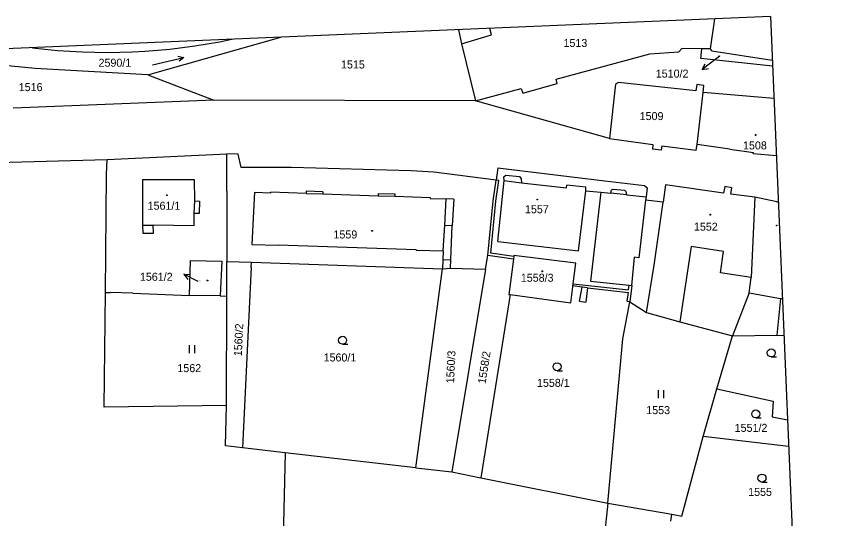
# Model space of a CAD drawing. Extents: x -806456 to -805395, y -1150847 to -1150506.
# Drawn here: x -805548.5 to -805394.6, y -1150600.2 to -1150506.1 of the extents above; entities that cross this region are included whole.
import ezdxf

# ---------------------------------------------------------------- set-up
doc = ezdxf.new("R2010")
doc.units = 0
for name, color, linetype in [('Default', 7, 'Continuous'), ('formát', 7, 'Continuous'), ('kn_celek - Cisla parcel pomocna', 7, 'Continuous'), ('kn_celek - Cisla pozemkovych parcel', 7, 'Continuous'), ('kn_celek - Cisla stavebnich parcel', 7, 'Continuous'), ('kn_celek - Hranice parcel', 7, 'Continuous'), ('kn_celek - Vnitrni kresby', 7, 'Continuous'), ('kn_celek - Znacky budov', 7, 'Continuous'), ('kn_celek - Znacky kultur', 7, 'Continuous')]:
    doc.layers.add(name, color=color, linetype=linetype)

# ---------------------------------------------------------------- blocks, each defined once
blk = doc.blocks.new('304')
at = {"layer": 'Default'}
blk.add_line((-0.1, 0), (9.9, 0), dxfattribs=at)
blk.add_circle((-0.1, 7.5), 7.5, dxfattribs=at)
blk = doc.blocks.new('306')
at = {"layer": 'Default'}
for p, q in [((-5.2, 0), (-5.2, 15)), ((4.8, 0), (4.8, 15))]:
    blk.add_line(p, q, dxfattribs=at)
blk = doc.blocks.new('402')
at = {"layer": 'Default'}
for p, q in [((-0.8, 0.8), (0.7, 0.8)), ((-0.8, 0.8), (-0.8, -0.7)), ((0.7, 0.8), (0.7, -0.7)), ((0.7, -0.7), (-0.8, -0.7))]:
    blk.add_line(p, q, dxfattribs=at)
blk = doc.blocks.new('Z61')
at = {"layer": 'Default'}
for p, q in [((0, 0), (30, 0)), ((30, 0), (19.2, 5.3)), ((30, 0), (19.2, -5.3))]:
    blk.add_line(p, q, dxfattribs=at)
blk = doc.blocks.new('802')
at = {"layer": 'Default'}
for p, q in [((-30, 0), (30, 0)), ((20, 5), (30, 0)), ((30, 0), (20, -5))]:
    blk.add_line(p, q, dxfattribs=at)

msp = doc.modelspace()

# ---------------------------------------------------------------- linework, layer by layer
at = {"layer": 'formát'}
for q in [(-805617.02, -1150514.97), (-805394.61, -1150802.8)]:
    msp.add_line((-805407.21, -1150506.06), q, dxfattribs=at)
at = {"layer": 'kn_celek - Cisla parcel pomocna'}
msp.add_line((-805416.7, -1150513.5), (-805417.6, -1150514.2), dxfattribs=at)
at = {"layer": 'kn_celek - Hranice parcel'}
for p, q in [((-805418.45, -1150512.13), (-805417.6, -1150506.5)), ((-805465.68, -1150508.55), (-805465.08, -1150511.17)), ((-805459.51, -1150509.54), (-805459.82, -1150508.3)), ((-805523.89, -1150516.99), (-805498.97, -1150509.96)), ((-805465.08, -1150511.17), (-805459.51, -1150509.54)), ((-805465.08, -1150511.17), (-805462.51, -1150521.87)), ((-805424.36, -1150512.68), (-805423.78, -1150512.05)), ((-805420.06, -1150512.11), (-805423.78, -1150512.05)), ((-805420.27, -1150513.95), (-805420.06, -1150512.11)), ((-805418.45, -1150512.13), (-805420.06, -1150512.11)), ((-805418.16, -1150512.5), (-805418.45, -1150512.13)), ((-805545.02, -1150515.82), (-805573.69, -1150513.13)), ((-805434.17, -1150514.23), (-805429.79, -1150513.09)), ((-805429.79, -1150513.09), (-805424.36, -1150512.68)), ((-805406.81, -1150515.36), (-805420.27, -1150513.95)), ((-805418.16, -1150512.5), (-805406.86, -1150514.24)), ((-805447.37, -1150517.8), (-805434.17, -1150514.23)), ((-805523.89, -1150516.99), (-805545.02, -1150515.82)), ((-805523.89, -1150516.99), (-805511.56, -1150521.75)), ((-805447.18, -1150518.66), (-805447.37, -1150517.8)), ((-805435.67, -1150518.44), (-805436.25, -1150518.74)), ((-805421.2, -1150520), (-805435.67, -1150518.44)), ((-805462.51, -1150521.87), (-805453.91, -1150519.58)), ((-805453.91, -1150519.58), (-805453.6, -1150520.47)), ((-805453.6, -1150520.47), (-805447.18, -1150518.66)), ((-805436.25, -1150518.74), (-805437.39, -1150528.93)), ((-805420.99, -1150518.84), (-805421.2, -1150520)), ((-805419.68, -1150518.99), (-805420.99, -1150518.84)), ((-805419.83, -1150520.32), (-805419.68, -1150518.99)), ((-805420.95, -1150530.06), (-805419.83, -1150520.32)), ((-805406.55, -1150521.42), (-805419.83, -1150520.32)), ((-805511.56, -1150521.75), (-805549.13, -1150523.27)), ((-805462.51, -1150521.87), (-805511.56, -1150521.75)), ((-805437.39, -1150528.93), (-805462.51, -1150521.87)), ((-805437.39, -1150528.93), (-805429.24, -1150530.06)), ((-805429.24, -1150530.06), (-805429.33, -1150530.91)), ((-805427.7, -1150531.12), (-805429.33, -1150530.91)), ((-805427.53, -1150530.33), (-805427.7, -1150531.12)), ((-805427.53, -1150530.33), (-805421.13, -1150531.13)), ((-805421.13, -1150531.13), (-805420.95, -1150530.06)), ((-805414.8, -1150530.96), (-805420.95, -1150530.06)), ((-805414.8, -1150530.96), (-805410.39, -1150531.59)), ((-805531.55, -1150532.9), (-805509.09, -1150531.8)), ((-805506.98, -1150531.87), (-805509.09, -1150531.8)), ((-805509.09, -1150534.77), (-805509.09, -1150531.8)), ((-805506.43, -1150534.35), (-805506.98, -1150531.87)), ((-805410.42, -1150531.81), (-805410.39, -1150531.59)), ((-805406.1, -1150532.2), (-805410.42, -1150531.81)), ((-805552.74, -1150533.48), (-805531.55, -1150532.9)), ((-805531.63, -1150535.7), (-805531.55, -1150532.9)), ((-805509.1, -1150538.82), (-805509.09, -1150534.77)), ((-805496.95, -1150534.39), (-805506.43, -1150534.35)), ((-805492.41, -1150534.52), (-805496.95, -1150534.39)), ((-805479.1, -1150534.87), (-805492.41, -1150534.52)), ((-805474.57, -1150534.98), (-805479.1, -1150534.87)), ((-805470.31, -1150535.26), (-805474.57, -1150534.98)), ((-805458.6, -1150536.72), (-805470.31, -1150535.26)), ((-805458.32, -1150534.47), (-805458.6, -1150536.72)), ((-805458.32, -1150534.47), (-805442.37, -1150536.36)), ((-805531.85, -1150557.78), (-805531.63, -1150535.7)), ((-805459.17, -1150540.62), (-805458.6, -1150536.72)), ((-805442.37, -1150536.36), (-805438.22, -1150536.87)), ((-805438.22, -1150536.87), (-805430.82, -1150537.74)), ((-805430.82, -1150537.74), (-805430.33, -1150538.18)), ((-805430.33, -1150538.18), (-805430.52, -1150539.85)), ((-805426.87, -1150537.61), (-805427.33, -1150540.86)), ((-805416.02, -1150539.19), (-805426.87, -1150537.61)), ((-805415.77, -1150537.95), (-805416.02, -1150539.19)), ((-805414.46, -1150538.19), (-805415.77, -1150537.95)), ((-805414.59, -1150539.39), (-805414.46, -1150538.19)), ((-805509.1, -1150538.82), (-805509.12, -1150551.97)), ((-805430.52, -1150539.85), (-805430.6, -1150540.49)), ((-805410.1, -1150539.94), (-805414.59, -1150539.39)), ((-805410.1, -1150539.94), (-805410.81, -1150554.99)), ((-805405.98, -1150540.8), (-805410.1, -1150539.94)), ((-805460.18, -1150550.87), (-805459.17, -1150540.62)), ((-805430.6, -1150540.49), (-805431.86, -1150551.3)), ((-805427.33, -1150540.86), (-805430.6, -1150540.49)), ((-805405.98, -1150540.8), (-805405.73, -1150540.83)), ((-805460.61, -1150553.45), (-805460.18, -1150550.87)), ((-805455.39, -1150551.57), (-805460.18, -1150550.87)), ((-805455.3, -1150550.87), (-805455.32, -1150551.04)), ((-805443.69, -1150552.31), (-805455.3, -1150550.87)), ((-805516.08, -1150558.34), (-805515.92, -1150551.82)), ((-805515.92, -1150551.82), (-805510.02, -1150551.94)), ((-805510.02, -1150551.94), (-805510.34, -1150558.45)), ((-805509.13, -1150558.47), (-805509.12, -1150551.97)), ((-805509.12, -1150551.97), (-805504.5, -1150552.13)), ((-805504.54, -1150553.06), (-805504.5, -1150552.13)), ((-805504.5, -1150552.13), (-805468.7, -1150553.35)), ((-805455.39, -1150551.57), (-805456.22, -1150558.16)), ((-805455.32, -1150551.04), (-805455.39, -1150551.57)), ((-805444.17, -1150556.16), (-805443.69, -1150552.31)), ((-805433.2, -1150556.49), (-805432.65, -1150551.21)), ((-805431.86, -1150551.3), (-805432.65, -1150551.21)), ((-805504.54, -1150553.06), (-805506.16, -1150586.91)), ((-805473.68, -1150590.65), (-805468.7, -1150553.35)), ((-805468.7, -1150553.35), (-805467.17, -1150553.25)), ((-805467.17, -1150553.25), (-805460.61, -1150553.45)), ((-805460.61, -1150553.45), (-805466.95, -1150591.42)), ((-805411.2, -1150557.84), (-805410.81, -1150554.99)), ((-805444.62, -1150559.77), (-805444.24, -1150556.76)), ((-805444.24, -1150556.76), (-805444.22, -1150556.58)), ((-805444.22, -1150556.58), (-805444.17, -1150556.16)), ((-805442.51, -1150556.81), (-805444.22, -1150556.58)), ((-805442.99, -1150559.46), (-805442.51, -1150556.81)), ((-805441.51, -1150556.92), (-805441.79, -1150559.61)), ((-805441.51, -1150556.92), (-805433.8, -1150557.81)), ((-805433.2, -1150556.49), (-805433.55, -1150559.55)), ((-805532.07, -1150579.27), (-805531.85, -1150557.78)), ((-805531.85, -1150557.78), (-805530.91, -1150557.81)), ((-805526.7, -1150557.96), (-805530.91, -1150557.81)), ((-805526.7, -1150557.96), (-805516.08, -1150558.34)), ((-805510.34, -1150558.45), (-805516.08, -1150558.34)), ((-805510.34, -1150558.45), (-805509.13, -1150558.47)), ((-805509.15, -1150578.97), (-805509.13, -1150558.47)), ((-805455.99, -1150558.2), (-805461.49, -1150592.52)), ((-805456.22, -1150558.16), (-805455.99, -1150558.2)), ((-805455.99, -1150558.2), (-805444.62, -1150559.77)), ((-805434.03, -1150559.5), (-805433.8, -1150557.81)), ((-805411.2, -1150557.84), (-805414.3, -1150565.9)), ((-805442.99, -1150559.46), (-805441.79, -1150559.61)), ((-805434.86, -1150566.49), (-805433.55, -1150559.55)), ((-805433.55, -1150559.55), (-805434.03, -1150559.5)), ((-805433.55, -1150559.55), (-805430.41, -1150561.57)), ((-805430.41, -1150561.57), (-805424.21, -1150563.29)), ((-805424.21, -1150563.29), (-805414.3, -1150565.9)), ((-805417.22, -1150575.88), (-805414.3, -1150565.9)), ((-805414.3, -1150565.9), (-805405.97, -1150565.79)), ((-805405.97, -1150565.79), (-805404.67, -1150565.84)), ((-805437.68, -1150597.31), (-805434.86, -1150566.49)), ((-805419.83, -1150584.77), (-805417.22, -1150575.88)), ((-805417.22, -1150575.88), (-805406.71, -1150578.2)), ((-805406.71, -1150578.2), (-805406.9, -1150581.1)), ((-805509.15, -1150578.97), (-805532.07, -1150579.27)), ((-805509.35, -1150586.54), (-805509.15, -1150578.97)), ((-805406.9, -1150581.1), (-805404, -1150581.65)), ((-805423.81, -1150599.71), (-805419.83, -1150584.77)), ((-805403.78, -1150586.66), (-805419.83, -1150584.77)), ((-805506.16, -1150586.91), (-805509.35, -1150586.54)), ((-805498.17, -1150587.83), (-805506.16, -1150586.91)), ((-805498.17, -1150587.83), (-805498.93, -1150623.15)), ((-805473.68, -1150590.65), (-805498.17, -1150587.83)), ((-805473.68, -1150590.65), (-805466.95, -1150591.42)), ((-805466.95, -1150591.42), (-805461.49, -1150592.52)), ((-805461.49, -1150592.52), (-805437.68, -1150597.31)), ((-805437.68, -1150597.31), (-805443.12, -1150647.75)), ((-805437.68, -1150597.31), (-805425.71, -1150599.38)), ((-805425.86, -1150600.64), (-805425.71, -1150599.38)), ((-805425.71, -1150599.38), (-805423.81, -1150599.71))]:
    msp.add_line(p, q, dxfattribs=at)
at = {"layer": 'kn_celek - Vnitrni kresby'}
for p, q in [((-805524.89, -1150536.62), (-805524.91, -1150545.19)), ((-805524.89, -1150536.62), (-805515.24, -1150536.65)), ((-805515.24, -1150536.65), (-805515.19, -1150540.64)), ((-805458.68, -1150540.69), (-805458.11, -1150536.79)), ((-805458.11, -1150536.79), (-805458.6, -1150536.72)), ((-805458.29, -1150548.25), (-805457.14, -1150536.84)), ((-805457.16, -1150536.13), (-805456.81, -1150535.82)), ((-805457.14, -1150536.84), (-805457.16, -1150536.13)), ((-805457.14, -1150536.84), (-805453.89, -1150537.22)), ((-805456.81, -1150535.82), (-805454.24, -1150536.08)), ((-805454.24, -1150536.08), (-805453.91, -1150536.48)), ((-805453.91, -1150536.48), (-805453.89, -1150537.22)), ((-805453.89, -1150537.22), (-805445.44, -1150538.21)), ((-805445.44, -1150538.21), (-805445.38, -1150537.71)), ((-805441.78, -1150538.07), (-805445.38, -1150537.71)), ((-805441.79, -1150538.76), (-805441.78, -1150538.07)), ((-805437.1, -1150539.21), (-805436.96, -1150538.55)), ((-805436.96, -1150538.55), (-805436.65, -1150538.41)), ((-805436.65, -1150538.41), (-805434.57, -1150538.62)), ((-805434.57, -1150538.62), (-805434.31, -1150538.89)), ((-805503.94, -1150539), (-805504.43, -1150548.79)), ((-805503.94, -1150539), (-805500.84, -1150539.11)), ((-805494.21, -1150539.23), (-805500.84, -1150539.01)), ((-805500.84, -1150539.11), (-805500.84, -1150539.01)), ((-805494.2, -1150538.83), (-805494.21, -1150539.23)), ((-805494.21, -1150539.23), (-805491.11, -1150539.33)), ((-805491.1, -1150538.93), (-805494.2, -1150538.83)), ((-805491.1, -1150538.93), (-805491.11, -1150539.33)), ((-805491.11, -1150539.33), (-805480.73, -1150539.67)), ((-805480.73, -1150539.28), (-805477.6, -1150539.3)), ((-805480.73, -1150539.28), (-805480.73, -1150539.67)), ((-805480.73, -1150539.67), (-805477.6, -1150539.77)), ((-805477.6, -1150539.3), (-805477.6, -1150539.77)), ((-805477.6, -1150539.77), (-805470.98, -1150539.99)), ((-805470.98, -1150539.99), (-805470.97, -1150540.17)), ((-805470.97, -1150540.17), (-805468, -1150540.27)), ((-805443.17, -1150549.97), (-805441.79, -1150538.76)), ((-805441.79, -1150538.76), (-805438.99, -1150539.03)), ((-805438.99, -1150539.03), (-805440.91, -1150555.69)), ((-805438.99, -1150539.03), (-805437.1, -1150539.21)), ((-805434.2, -1150539.49), (-805437.1, -1150539.21)), ((-805434.31, -1150538.89), (-805434.2, -1150539.49)), ((-805434.2, -1150539.49), (-805430.52, -1150539.85)), ((-805515.19, -1150540.64), (-805515.27, -1150542.99)), ((-805515.19, -1150540.64), (-805514.21, -1150540.67)), ((-805514.21, -1150540.67), (-805514.27, -1150543)), ((-805468.22, -1150545.16), (-805468, -1150540.27)), ((-805466.52, -1150540.33), (-805468, -1150540.27)), ((-805466.52, -1150540.33), (-805466.84, -1150545.25)), ((-805459.63, -1150550.42), (-805458.68, -1150540.69)), ((-805429.02, -1150552.71), (-805427.33, -1150540.86)), ((-805515.27, -1150542.99), (-805515.31, -1150545.28)), ((-805514.27, -1150543), (-805515.27, -1150542.99)), ((-805524.91, -1150545.19), (-805524.86, -1150546.66)), ((-805524.91, -1150545.19), (-805522.89, -1150545.2)), ((-805515.31, -1150545.28), (-805522.89, -1150545.2)), ((-805522.83, -1150546.66), (-805522.89, -1150545.2)), ((-805468.57, -1150550.01), (-805468.22, -1150545.16)), ((-805468.22, -1150545.16), (-805466.84, -1150545.25)), ((-805467.08, -1150551.6), (-805466.84, -1150545.25)), ((-805524.86, -1150546.66), (-805522.83, -1150546.66)), ((-805504.43, -1150548.79), (-805499.48, -1150548.96)), ((-805499.48, -1150548.86), (-805473.58, -1150549.74)), ((-805499.48, -1150548.96), (-805499.48, -1150548.86)), ((-805458.29, -1150548.25), (-805443.17, -1150549.97)), ((-805422.07, -1150549.17), (-805424.21, -1150563.29)), ((-805415.98, -1150550.09), (-805422.07, -1150549.17)), ((-805473.58, -1150549.84), (-805473.58, -1150549.74)), ((-805473.58, -1150549.84), (-805468.57, -1150550.01)), ((-805468.57, -1150550.01), (-805468.62, -1150551.68)), ((-805455.32, -1150551.04), (-805459.63, -1150550.42)), ((-805416.53, -1150554.11), (-805415.98, -1150550.09)), ((-805468.62, -1150551.68), (-805468.7, -1150553.35)), ((-805468.62, -1150551.68), (-805467.08, -1150551.6)), ((-805467.17, -1150553.25), (-805467.08, -1150551.6)), ((-805430.41, -1150561.57), (-805429.02, -1150552.71)), ((-805410.81, -1150554.99), (-805416.53, -1150554.11)), ((-805444.17, -1150556.16), (-805433.78, -1150557.3)), ((-805441.51, -1150556.92), (-805442.51, -1150556.81)), ((-805440.91, -1150555.69), (-805433.7, -1150556.44)), ((-805433.78, -1150557.3), (-805433.7, -1150556.44)), ((-805433.7, -1150556.44), (-805433.2, -1150556.49)), ((-805411.2, -1150557.84), (-805405.34, -1150558.91)), ((-805405.34, -1150558.91), (-805405.97, -1150565.79)), ((-805405.34, -1150558.91), (-805404.96, -1150558.95))]:
    msp.add_line(p, q, dxfattribs=at)
msp.add_arc((-805531.59, -1150399.65), 113.15, 262.9118, 281.9498, dxfattribs=at)
msp.add_arc((-805531.59, -1150399.65), 113.15, 262.9118, 281.9498, dxfattribs=at)

# ---------------------------------------------------------------- block references
at = {"layer": 'kn_celek - Cisla parcel pomocna'}
for p, xscale, yscale, rotation in [((-805417.6, -1150514.2), 0.1, 0.10000000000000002, -142.35543), ((-805514.48, -1150555.74), 0.09999999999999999, 0.09999999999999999, 153.43497)]:
    msp.add_blockref('Z61', p, dxfattribs=dict(at, xscale=xscale, yscale=yscale, rotation=rotation))
at = {"layer": 'kn_celek - Znacky budov', "xscale": 0.1, "yscale": 0.10000000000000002}
for p in [(-805409.98, -1150528.29), (-805520.35, -1150539.56), (-805450.91, -1150540.38), (-805418.48, -1150543.22), (-805481.89, -1150546.27), (-805406.04, -1150545.24), (-805449.97, -1150553.85), (-805512.76, -1150555.55)]:
    msp.add_blockref('402', p, dxfattribs=at)
at = {"layer": 'kn_celek - Znacky kultur', "xscale": 0.1, "yscale": 0.10000000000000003, "rotation": 13.362932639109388}
msp.add_blockref('802', (-805520.1, -1150514.44), dxfattribs=at)
at = {"layer": 'kn_celek - Znacky kultur', "xscale": 0.1, "yscale": 0.10000000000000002}
for name, p in [('304', (-805487.39, -1150567.5)), ('306', (-805515.55, -1150569.17)), ('304', (-805407.03, -1150569.87)), ('304', (-805447.18, -1150572.47)), ('306', (-805427.67, -1150577.58)), ('304', (-805409.94, -1150581.32)), ('304', (-805408.77, -1150593.33))]:
    msp.add_blockref(name, p, dxfattribs=at)

# ---------------------------------------------------------------- texts
at = {"layer": 'kn_celek - Cisla parcel pomocna'}
for s, p in [('1510/2', (-805428.69, -1150517.53)), ('1561/2', (-805525.4, -1150555.61))]:
    msp.add_text(s, height=1.5, dxfattribs=at).set_placement(p)
at = {"layer": 'kn_celek - Cisla pozemkovych parcel'}
for s, height, p in [('1513', 1.5, (-805445.99, -1150511.79)), ('2590/1', 1.5, (-805533.15, -1150515.49)), ('1510/2', 0.1, (-805416.96, -1150513.47)), ('1515', 1.5, (-805487.7, -1150515.82)), ('1516', 1.5, (-805548.11, -1150520.06)), ('1509', 1.5, (-805431.71, -1150525.49)), ('1560/1', 1.5, (-805490.96, -1150570.73)), ('1562', 1.5, (-805518.37, -1150572.73)), ('1558/1', 1.5, (-805450.96, -1150575.49)), ('1553', 1.5, (-805430.48, -1150580.6)), ('1551/2', 1.5, (-805413.9, -1150583.92)), ('1555', 1.5, (-805411.37, -1150595.93))]:
    msp.add_text(s, height=height, dxfattribs=at).set_placement(p)
for s, rotation, p in [('1560/2', 87.3, (-805506.3, -1150569.78)), ('1560/3', 87.3, (-805466.51, -1150574.86)), ('1558/2', 81, (-805460.6, -1150575))]:
    msp.add_text(s, height=1.5, rotation=rotation, dxfattribs=at).set_placement(p)
at = {"layer": 'kn_celek - Cisla stavebnich parcel'}
for s, height, p in [('1508', 1.5, (-805412.33, -1150530.99)), ('1561/1', 1.5, (-805523.95, -1150542.29)), ('1557', 1.5, (-805453.21, -1150542.95)), ('1552', 1.5, (-805421.54, -1150546.22)), ('1559', 1.5, (-805489.11, -1150547.68)), ('1558/3', 1.5, (-805453.99, -1150555.79)), ('1561/2', 0.1, (-805514.48, -1150555.71))]:
    msp.add_text(s, height=height, dxfattribs=at).set_placement(p)

doc.saveas('drawing.dxf')
